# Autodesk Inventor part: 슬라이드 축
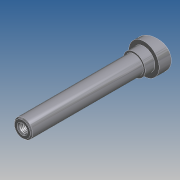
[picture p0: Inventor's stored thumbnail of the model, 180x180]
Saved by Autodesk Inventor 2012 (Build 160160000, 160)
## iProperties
Company: 한국ATC센터
Created: 2014-07
Part Number: 슬라이드 축
Document SubType Name: 모델링
Designer: KYOUNG IL JANG
Mass: 21.572 g
Surface Area: 67.5855 cm^2
Volume: 21.572 cm^3
Density: 1 g/cm^3
Material: 기본값
변환 표준: STEP AP214IS
파일 이름: C:\Users\SeoGD\Desktop\?쒗뿕\異?stp
전처리기: Build: 253, Release: 2010 SP1 - Date: Wed 07/29/2009
전송 단위: 밀리미터
불확실성: 0.01
Author: KYOUNG IL JANG
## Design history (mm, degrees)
sketch "스케치1"
  geometry: L1 (0, 100)-(7.5, 100); L2 (7.5, 100)-(7.5, 0); L3 (7.5, 0)-(12.5, 0); L4 (12.5, 0)-(12.5, -17); L5 (12.5, -17)-(0, -17); L6 (0, -17)-(0, 100); 1 further point
  constraints: 12 end point, 2 parallel, 2 point on line, 1 perpendicular, 1 vertical
  dimensions: "d0" = 100 distance from line of L1 point (0, 0); "d1" = 15 diameter of L2 L6; "d2" = 25 diameter of L4 L6; "d3" = 17 distance of L3.end L4.end
revolve "회전1" sketch "스케치1" stored, may be unused: angle "d4" = 90 deg
sketch "스케치2"
  geometry: L1 (12.5, 0)-(12.5, -17) reference; L2 (-12.5, -17)-(12.5, -17) reference; L3 (-12.5, 0)-(-12.5, -17) reference; L4 (12.5, -5)-(-12.5, -11.699); L5 (-12.5, 0)-(12.5, 0) reference; 1 further point
  constraints: 2 end point, 2 point on line
  dimensions: "d5" = 75 deg angle of L1 L4; "d6" = 5 distance from line of L4.start L5
extrude "돌출1" cut sketch "스케치2" stored distance "d7" = 10; taper "d8" = 0 deg
chamfer "모따기1" distance "d9" = 1; stored, may be unused: second distance "d10" = 2, angle "d11" = 45 deg
fillet "모깎기1" dims "d12" = 0.5
hole "구멍1" diameter "d15" = 6.647; stored, may be unused: countersink angle "d19" = 90 deg, drill point angle "d21" = 118 deg; dims "d13" = 10, "d14" = 10, "d16" = 17, "d17" = 4, "d18" = 2, "d20" = 20
chamfer "모따기2" distance "d22" = 1; stored, may be unused: second distance "d23" = 2, angle "d24" = 45 deg
sketch "스케치3"
  geometry: C1 r 9 at (0, 0); 1 further point
  constraints: 1 centre point, 1 coincident
  dimensions: "d25" = 18 diameter of C1
extrude "돌출2" join sketch "스케치3" distance "d26" = 8; taper "d27" = 0 deg
node "솔리드1"
node "솔리드 본체"
node "곡면 본체"
node "솔리드2"
